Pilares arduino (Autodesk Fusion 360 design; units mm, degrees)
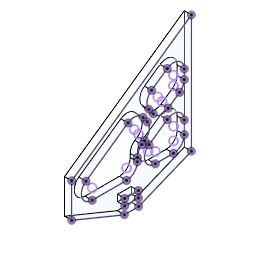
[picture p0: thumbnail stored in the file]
part number: 2026-07-18-00-36-09-592
sketch "Boceto1" plane through (0, 0, 0) normal (0, 0, 1) x axis (1, 0, 0)
  line L1 (3, 0) -> (0, 0)
  line L2 (3, 50) -> (3, 0)
  line L3 (0, 50) -> (3, 50)
  line L4 (0, 0) -> (0, 50)
  point P1 (0, 0)
  point P2 (0, 0)
  point P3 (3, 0)
  point P4 (3, 50)
  coincident P1 P2
  horizontal L1
  perpendicular L1 L2
  perpendicular L2 L3
  perpendicular L1 L4
  dimension "d1" distance P2 P3 = 3
  dimension "d2" distance P3 P4 = 50
extrude "Extruir1" new body sketch "Boceto1" along normal blind 62
sketch "Boceto2" plane through (3, 0, 0) normal (1, 0, 0) x axis (0, 1, 0)
  line L1 (50, 0) -> (0, 0)
  line L2 (50, 62) -> (50, 0)
  line L3 (0, 62) -> (50, 62)
  line L4 (0, 0) -> (0, 62)
  line L5 (50, 9) -> (50, 0)
  line L6 (25, 0) -> (50, 0)
  line L7 (28, 0) -> (25, 0)
  line L8 (50, 9) -> (28, 0)
  line L9 (22, 0) -> (25, 0)
  line L10 (0, 9) -> (0, 0)
  line L11 (22, 0) -> (0, 9)
  line L12 (0, 0) -> (22, 0)
  point P3 (50, 0)
  point P6 (50, 0)
  point P8 (25, 0)
  point P9 (28, 0)
  point P10 (22, 0)
  point P2 (0, 0)
  point P11 (0, 0)
  point P12 (0, 9)
  point P13 (0, 0)
  point P7 (50, 9)
  coincident P3 P6
  perpendicular L1 L5
  midpoint L1 P8
  coincident L1 P9
  coincident L1 P10
  coincident P2 P11
  coincident L4 P12
  coincident P2 P13
  dimension "d5" distance P6 P7 = 9
extrude "Extruir2" cut sketch "Boceto2" profile of L1 L2 L4 L5 L6 L8 L10 L11 L12 against normal blind 6
sketch "Boceto3" plane through (3, 0, 0) normal (1, 0, 0) x axis (0, 1, 0)
  line L1 (22, 0) -> (0, 9)
  line L2 (28, 0) -> (22, 0)
  line L3 (50, 9) -> (28, 0)
  line L4 (50, 62) -> (50, 9)
  line L5 (0, 62) -> (50, 62)
  line L6 (0, 9) -> (0, 62)
  line L7 (0, 24) -> (0, 9)
  line L8 (50, 62) -> (0, 24)
  line L9 (0, 62) -> (50, 62)
  line L10 (0, 24) -> (0, 62)
  point P2 (0, 9)
  point P8 (0, 9)
  point P6 (50, 62)
  point P10 (50, 62)
  point P11 (50, 62)
  point P7 (0, 62)
  point P12 (0, 62)
  point P13 (0, 62)
  point P9 (0, 24)
  coincident P2 P8
  parallel L6 L7
  coincident P6 P10
  coincident P6 P11
  coincident P7 P12
  coincident P7 P13
  dimension "d8" distance P8 P9 = 15
extrude "Extruir3" cut sketch "Boceto3" profile of L5 L6 L8 L9 L10 against normal blind 6
sketch "Boceto4" plane through (3, 0, 0) normal (1, 0, 0) x axis (0, 1, 0)
  line L1 (0, 24) -> (50, 62)
  line L2 (0, 9) -> (0, 24)
  line L3 (22, 0) -> (0, 9)
  line L4 (28, 0) -> (22, 0)
  line L5 (50, 9) -> (28, 0)
  line L6 (50, 62) -> (50, 9)
  line L7 (0, 27) -> (0, 9)
  line L8 (50, 65) -> (50, 9)
  line L9 (0, 27) -> (50, 65)
  point P4 (0, 9)
  point P8 (0, 9)
  point P7 (50, 9)
  point P10 (50, 9)
  point P9 (0, 27)
  point P11 (50, 65)
  coincident P4 P8
  parallel L2 L7
  coincident P7 P10
  parallel L6 L8
  dimension "d11" distance P8 P9 = 18
  dimension "d12" distance P10 P11 = 56
extrude "Extruir4" add sketch "Boceto4" profile of L1 L7 L8 L9 against normal blind 3
sketch "Boceto5" plane through (3, 0, 0) normal (1, 0, 0) x axis (0, 1, 0)
  line L1 (0, 9) -> (0, 27)
  line L2 (22, 0) -> (0, 9)
  line L3 (28, 0) -> (22, 0)
  line L4 (50, 9) -> (28, 0)
  line L5 (50, 65) -> (50, 9)
  line L6 (0, 27) -> (50, 65)
  line L7 (50, 62) -> (0, 27)
  line L8 (50, 62) -> (50, 65)
  line L9 (0, 27) -> (50, 65)
  point P2 (0, 27)
  point P8 (0, 27)
  point P9 (50, 62)
  point P7 (50, 65)
  point P10 (50, 65)
  point P11 (50, 65)
  point P12 (0, 27)
  coincident P2 P8
  coincident L5 P9
  coincident P7 P10
  coincident P7 P11
  coincident P2 P12
extrude "Extruir5" cut sketch "Boceto5" profile of L5 L6 L7 L8 L9 against normal blind 6
sketch "Boceto6" plane through (3, 0, 0) normal (1, 0, 0) x axis (0, 1, 0)
  line L1 (0, 27) -> (50, 62)
  line L2 (0, 9) -> (0, 27)
  line L3 (22, 0) -> (0, 9)
  line L4 (28, 0) -> (22, 0)
  line L5 (50, 9) -> (28, 0)
  line L6 (50, 62) -> (50, 9)
  line L7 (0, 12) -> (0, 9)
  line L8 (50, 12) -> (0, 12)
  line L9 (50, 12) -> (50, 9)
  line L10 (26.7204, 42.0423) -> (25, 44.5)
  line L11 (50, 58.338) -> (26.7204, 42.0423)
  line L12 (0, 23.338) -> (26.7204, 42.0423)
  line L13 (47, 12) -> (50, 12)
  line L14 (47, 56.238) -> (47, 12)
  line L15 (3, 12) -> (0, 12)
  line L16 (3, 25.438) -> (3, 12)
  line L17 (25, 12) -> (3, 12)
  line L18 (47, 34.119) -> (47, 56.238)
  line L19 (47, 34.119) -> (47, 56.238)
  line L20 (15.4, 12) -> (47, 34.119)
  line L21 (32.9203, 20.6018) -> (31.2, 23.0595)
  line L22 (47, 30.4571) -> (32.9203, 20.6018)
  line L23 (25.2826, 15.2556) -> (32.9203, 20.6018)
  line L24 (20.7418, 12.0772) -> (25.2826, 15.2556)
  line L25 (15.4, 12) -> (47, 34.119)
  line L26 (20.6315, 12) -> (15.4, 12)
  line L27 (47, 30.4571) -> (20.6315, 12)
  line L28 (39.9602, 25.5294) -> (32.9203, 20.6018)
  circle C1 centre (42.5, 21.8144) radius 4.5
  circle C2 centre (42.5, 16.5) radius 4.5
  circle C3 centre (34.9077, 16.5) radius 4.5
  circle C4 centre (42.5, 47.5951) radius 4.5
  circle C5 centre (42.5, 36.462) radius 4.5
  circle C6 centre (7.5, 16.5) radius 4.5
  circle C7 centre (7.5, 23.0951) radius 4.5
  circle C8 centre (13.9816, 16.5) radius 4.5
  point P4 (0, 9)
  point P8 (0, 9)
  point P9 (0, 12)
  point P10 (50, 12)
  point P7 (50, 9)
  point P11 (50, 9)
  point P12 (25, 44.5)
  point P14 (50, 58.338)
  point P15 (0, 23.338)
  point P16 (47, 12)
  point P17 (47, 56.238)
  point P18 (3, 12)
  point P19 (3, 25.438)
  point P20 (25, 12)
  point P21 (47, 34.119)
  point P22 (15.4, 12)
  point P23 (31.2, 23.0595)
  point P25 (47, 30.4571)
  point P28 (20.6315, 12)
  point P29 (39.9602, 25.5294)
  point P13 (26.7204, 42.0423)
  point P24 (32.9203, 20.6018)
  coincident P4 P8
  coincident L2 P9
  coincident L6 P10
  perpendicular L6 L8
  coincident P7 P11
  midpoint L1 P12
  perpendicular L1 L10
  coincident L6 P14
  perpendicular L10 L11
  coincident L2 P15
  perpendicular L10 L12
  coincident L8 P16
  coincident L11 P17
  perpendicular L13 L14
  coincident L8 P18
  coincident L12 P19
  perpendicular L15 L16
  midpoint L8 P20
  midpoint L14 P21
  coincident L8 P22
  midpoint L20 P23
  perpendicular L20 L21
  coincident L14 P25
  perpendicular L21 L22
  perpendicular L21 L23
  parallel L23 L24
  coincident L17 P28
  midpoint L22 P29
  tangent L28 C1
  tangent L14 C1
  tangent L14 C2
  tangent L8 C2
  tangent L8 C3
  tangent L23 C3
  tangent L14 C4
  tangent L11 C4
  tangent L25 C5
  tangent L18 C5
  tangent L12 C7
  tangent L16 C7
  tangent L16 C6
  tangent L17 C6
  tangent L8 C8
  tangent L20 C8
  dimension "d17" distance P12 P13 = 3
  dimension "d18" distance P23 P24 = 3
  dimension "d19" diameter C1 = 9
  dimension "d20" diameter C2 = 9
  dimension "d21" diameter C3 = 9
  dimension "d22" diameter C4 = 9
  dimension "d23" diameter C5 = 9
  dimension "d24" diameter C6 = 9
  dimension "d25" diameter C7 = 9
  dimension "d26" diameter C8 = 9
extrude "Extruir6" cut sketch "Boceto6" profile of L8 L11 L12 L14 L16 L17 L18 L19 L20 L22 L23 L25 L27 L28 C1 C2 C3 C4 C5 C6 C7 C8 against normal blind 6
sketch "Boceto7" plane through (3, 0, 0) normal (1, 0, 0) x axis (0, 1, 0)
  line L1 (7.5014, 12) -> (13.9822, 12)
  line L2 (3, 23.0951) -> (3, 16.5)
  line L3 (39.9194, 51.2816) -> (4.9194, 26.7816)
  line L4 (47, 36.462) -> (47, 47.5951)
  line L5 (16.5621, 12.8134) -> (45.0805, 32.7754)
  line L6 (34.9081, 12) -> (42.5006, 12)
  line L7 (39.9195, 25.501) -> (32.3272, 20.1866)
  line L8 (47, 16.5) -> (47, 21.8144)
  line L9 (0, 27) -> (50, 62)
  line L10 (0, 9) -> (0, 27)
  line L11 (22, 0) -> (0, 9)
  line L12 (28, 0) -> (22, 0)
  line L13 (50, 9) -> (28, 0)
  line L14 (50, 62) -> (50, 9)
  line L15 (22, 3) -> (22, 0)
  line L16 (28, 3) -> (22, 3)
  line L17 (28, 6) -> (28, 3)
  line L18 (22, 6) -> (28, 6)
  line L19 (22, 3) -> (22, 6)
  line L20 (22.1552, 5.8667) -> (22.1552, 3.1667)
  line L21 (27.8552, 3.1667) -> (27.8552, 5.8667)
  line L22 (22.1552, 3.1667) -> (27.8552, 3.1667)
  line L23 (27.8552, 5.8667) -> (22.1552, 5.8667)
  arc A1 centre (7.5, 16.5) radius 4.5 clockwise from (7.5014, 12) to (3, 16.5)
  arc A2 centre (7.5, 23.0951) radius 4.5 clockwise from (3, 23.0951) to (4.9194, 26.7816)
  arc A3 centre (42.5, 47.5951) radius 4.5 clockwise from (39.9194, 51.2816) to (47, 47.5951)
  arc A4 centre (42.5, 36.462) radius 4.5 clockwise from (47, 36.462) to (45.0805, 32.7754)
  arc A5 centre (13.9816, 16.5) radius 4.5 clockwise from (16.5621, 12.8134) to (13.9822, 12)
  arc A6 centre (34.9077, 16.5) radius 4.5 clockwise from (34.9081, 12) to (32.3272, 20.1866)
  arc A7 centre (42.5, 21.8144) radius 4.5 clockwise from (39.9195, 25.501) to (47, 21.8144)
  arc A8 centre (42.5, 16.5) radius 4.5 clockwise from (47, 16.5) to (42.5006, 12)
  point P29 (22, 0)
  point P32 (22, 0)
  coincident P29 P32
  perpendicular L12 L15
  perpendicular L15 L16
  perpendicular L16 L17
  perpendicular L17 L18
  perpendicular L16 L19
extrude "Extruir7" cut sketch "Boceto7" profile of L16 L17 L18 L19 against normal blind 6
sketch "Boceto8" plane through (3, 0, 0) normal (1, 0, 0) x axis (0, 1, 0)
  line L1 (22, 3) -> (28, 3)
  line L2 (22, 6) -> (22, 3)
  line L3 (28, 6) -> (22, 6)
  line L4 (28, 3) -> (28, 6)
  line L5 (7.5014, 12) -> (13.9822, 12)
  line L6 (3, 23.0951) -> (3, 16.5)
  line L7 (39.9194, 51.2816) -> (4.9194, 26.7816)
  line L8 (47, 36.462) -> (47, 47.5951)
  line L9 (16.5621, 12.8134) -> (45.0805, 32.7754)
  line L10 (34.9081, 12) -> (42.5006, 12)
  line L11 (39.9195, 25.501) -> (32.3272, 20.1866)
  line L12 (47, 16.5) -> (47, 21.8144)
  line L13 (0, 27) -> (50, 62)
  line L14 (0, 9) -> (0, 27)
  line L15 (22, 0) -> (0, 9)
  line L16 (28, 0) -> (22, 0)
  line L17 (50, 9) -> (28, 0)
  line L18 (50, 62) -> (50, 9)
  line L19 (39.9194, 51.2816) -> (4.9194, 26.7816)
  line L20 (57.0546, 63.2763) -> (39.9194, 51.2816)
  line L21 (-4.5642, 20.1431) -> (57.0546, 63.2763)
  line L22 (50, 35.5) -> (50, 58.338)
  line L23 (0, 13) -> (0, 23.338)
  line L24 (29.686, 36.7943) -> (26.2452, 41.7097)
  line L25 (41.9336, 45.3676) -> (29.686, 36.7943)
  line L26 (-9.9761, 9.0308) -> (41.9336, 45.3676)
  line L27 (67.0038, 62.9168) -> (-9.9761, 9.0308)
  line L28 (50, 62) -> (50, 58.338)
  line L29 (0, 27) -> (50, 62)
  line L30 (0, 23.338) -> (0, 27)
  line L31 (47, 57.2789) -> (47, 43)
  line L32 (3, 26.5) -> (3, 19.7975)
  line L33 (47, 39.5) -> (47, 48.9141)
  line L34 (3, 13.3175) -> (3, 26.5)
  line L35 (3, 12) -> (8.5412, 12)
  line L36 (3, 12) -> (3, 13.3175)
  arc A1 centre (7.5, 16.5) radius 4.5 clockwise from (7.5014, 12) to (3, 16.5)
  arc A2 centre (7.5, 23.0951) radius 4.5 clockwise from (3, 23.0951) to (4.9194, 26.7816)
  arc A3 centre (42.5, 47.5951) radius 4.5 clockwise from (39.9194, 51.2816) to (47, 47.5951)
  arc A4 centre (42.5, 36.462) radius 4.5 clockwise from (47, 36.462) to (45.0805, 32.7754)
  arc A5 centre (13.9816, 16.5) radius 4.5 clockwise from (16.5621, 12.8134) to (13.9822, 12)
  arc A6 centre (34.9077, 16.5) radius 4.5 clockwise from (34.9081, 12) to (32.3272, 20.1866)
  arc A7 centre (42.5, 21.8144) radius 4.5 clockwise from (39.9195, 25.501) to (47, 21.8144)
  arc A8 centre (42.5, 16.5) radius 4.5 clockwise from (47, 16.5) to (42.5006, 12)
  circle C1 centre (42.5, 40.2712) radius 4.5
  circle C2 centre (8.5412, 16.5) radius 4.5
  point P11 (4.9194, 26.7816)
  point P36 (4.9194, 26.7816)
  point P13 (39.9194, 51.2816)
  point P37 (39.9194, 51.2816)
  point P38 (39.9194, 51.2816)
  point P41 (50, 58.338)
  point P42 (50, 35.5)
  point P43 (0, 23.338)
  point P44 (0, 13)
  point P45 (26.2452, 41.7097)
  point P30 (50, 62)
  point P50 (50, 62)
  point P51 (50, 62)
  point P31 (0, 27)
  point P52 (0, 27)
  point P53 (0, 27)
  point P54 (47, 43)
  point P56 (3, 19.7975)
  point P58 (47, 48.9141)
  point P59 (47, 39.5)
  point P63 (8.5412, 12)
  point P46 (29.686, 36.7943)
  coincident P11 P36
  coincident P13 P37
  coincident P13 P38
  tangent A3 L20
  parallel L7 L21
  coincident L21 P41
  coincident L18 P41
  midpoint L18 P42
  coincident L14 P43
  coincident L21 P43
  coincident L14 P44
  midpoint L21 P45
  perpendicular L7 L24
  perpendicular L24 L25
  parallel L25 L26
  parallel L26 L27
  coincident P30 P50
  coincident P30 P51
  coincident P31 P52
  coincident P31 P53
  coincident L8 P54
  parallel L30 L31
  midpoint L6 P56
  parallel L6 L32
  coincident L27 P58
  coincident L31 P58
  coincident L8 P59
  parallel L33 L34
  tangent L33 C1
  tangent L27 C1
  tangent L26 C2
  tangent L5 C2
  coincident L5 P63
  coincident C2 P63
  tangent C2 L35
  parallel L5 L35
  parallel L34 L36
  dimension "d31" distance P45 P46 = 6
  dimension "d32" diameter C1 = 9
  dimension "d33" diameter C2 = 9
extrude "Extruir8" cut sketch "Boceto8" profile of L7 L13 L14 L18 L19 L20 L21 L28 L29 L30 against normal blind 6
extrude "Extruir9" add sketch "Boceto8" profile of L5 A1 L6 A2 L7 A3 L8 L19 L21 L24 L25 L26 L27 L31 L32 L33 L34 C1 C2 L35 against normal blind 3
sketch "Boceto9" plane through (3, 0, 0) normal (1, 0, 0) x axis (0, 1, 0)
  line L1 (47, 36.462) -> (47, 40.2712)
  line L2 (16.5621, 12.8134) -> (45.0805, 32.7754)
  line L3 (8.5412, 12) -> (13.9822, 12)
  line L4 (39.9194, 43.9577) -> (5.9606, 20.1865)
  line L5 (34.9081, 12) -> (42.5006, 12)
  line L6 (39.9195, 25.501) -> (32.3272, 20.1866)
  line L7 (47, 16.5) -> (47, 21.8144)
  line L8 (0, 23.338) -> (50, 58.338)
  line L9 (0, 9) -> (0, 23.338)
  line L10 (22, 0) -> (0, 9)
  line L11 (28, 0) -> (22, 0)
  line L12 (50, 9) -> (28, 0)
  line L13 (50, 58.338) -> (50, 9)
  line L14 (22, 3) -> (28, 3)
  line L15 (22, 6) -> (22, 3)
  line L16 (28, 6) -> (22, 6)
  line L17 (28, 3) -> (28, 6)
  line L18 (30.4077, 16.5) -> (47, 16.5)
  line L19 (27.4077, 16.5) -> (30.4077, 16.5)
  line L20 (27.4077, 20.405) -> (27.4077, 16.5)
  line L21 (27.4077, 12) -> (13.9822, 12)
  line L22 (27.4077, 16.5) -> (27.4077, 12)
  line L23 (13.9822, 12) -> (27.4077, 20.405)
  line L24 (22.9077, 16.5) -> (22.9077, 12)
  line L25 (16.5621, 12.8134) -> (45.0805, 32.7754)
  arc A1 centre (42.5, 36.462) radius 4.5 clockwise from (47, 36.462) to (45.0805, 32.7754)
  arc A2 centre (13.9816, 16.5) radius 4.5 clockwise from (16.5621, 12.8134) to (13.9822, 12)
  arc A3 centre (8.5412, 16.5) radius 4.5 clockwise from (8.5412, 12) to (5.9606, 20.1865)
  arc A4 centre (42.5, 40.2712) radius 4.5 clockwise from (39.9194, 43.9577) to (47, 40.2712)
  arc A5 centre (34.9077, 16.5) radius 4.5 clockwise from (34.9081, 12) to (32.3272, 20.1866)
  arc A6 centre (42.5, 21.8144) radius 4.5 clockwise from (39.9195, 25.501) to (47, 21.8144)
  arc A7 centre (42.5, 16.5) radius 4.5 clockwise from (47, 16.5) to (42.5006, 12)
  circle C1 centre (22.9077, 16.5) radius 4.5
  circle C2 centre (31.9077, 18.062) radius 4.5
  point P21 (47, 16.5)
  point P33 (47, 16.5)
  point P34 (30.4077, 16.5)
  point P36 (27.4077, 20.405)
  point P7 (13.9822, 12)
  point P37 (13.9822, 12)
  point P39 (13.9822, 12)
  point P40 (22.9077, 12)
  point P41 (22.9077, 16.5)
  point P42 (22.9077, 16.5)
  point P35 (27.4077, 16.5)
  coincident P21 P33
  coincident A5 P34
  perpendicular L7 L18
  parallel L18 L19
  coincident L2 P36
  perpendicular L19 L20
  coincident P7 P37
  perpendicular L20 L21
  perpendicular L19 L22
  coincident P7 P39
  coincident L21 P40
  perpendicular L21 L24
  coincident P41 P42
  tangent L22 C1
  tangent C2 L25
  tangent L20 C2
  dimension "d38" distance P34 P35 = 3
  dimension "d41" distance P40 P41 = 4.5
  dimension "d42" diameter C1 = 9
  dimension "d45" diameter C2 = 9
extrude "Extruir10" cut sketch "Boceto9" profile of L2 A2 L20 L21 L22 against normal blind 4
extrude "Extruir11" add sketch "Boceto9" profile of L21 L22 C1 against normal blind 3
extrude "Extruir12" cut sketch "Boceto9" profile of L2 L20 C2 L25 against normal blind 3
sketch "Boceto10" plane through (3, 0, 0) normal (1, 0, 0) x axis (0, 1, 0)
  line L1 (22, 3) -> (28, 3)
  line L2 (22, 6) -> (22, 3)
  line L3 (28, 6) -> (22, 6)
  line L4 (28, 3) -> (28, 6)
  line L5 (0, 23.338) -> (50, 58.338)
  line L6 (0, 9) -> (0, 23.338)
  line L7 (22, 0) -> (0, 9)
  line L8 (28, 0) -> (22, 0)
  line L9 (50, 9) -> (28, 0)
  line L10 (50, 58.338) -> (50, 9)
  line L11 (34.9081, 12) -> (42.5006, 12)
  line L12 (39.9195, 25.501) -> (32.3272, 20.1866)
  line L13 (47, 16.5) -> (47, 21.8144)
  line L14 (27.4077, 16.5) -> (27.4077, 18.062)
  line L15 (8.5412, 12) -> (22.9077, 12)
  line L16 (39.9194, 43.9577) -> (5.9606, 20.1865)
  line L17 (47, 36.462) -> (47, 40.2712)
  line L18 (29.3272, 21.7486) -> (45.0805, 32.7754)
  line L19 (39.9194, 43.9577) -> (5.9606, 20.1865)
  line L20 (28.4408, 35.9226) -> (25, 40.838)
  line L21 (29.6694, 36.7827) -> (36.62, 26.8533)
  line L22 (34.1622, 25.133) -> (30.6871, 30.0977)
  line L23 (27.2117, 35.0623) -> (34.1622, 25.133)
  line L24 (41.9336, 45.3676) -> (29.686, 36.7943)
  line L25 (16.5621, 12.8134) -> (45.0805, 32.7754)
  line L26 (67.0038, 62.9168) -> (-9.9761, 9.0308)
  arc A1 centre (34.9077, 16.5) radius 4.5 clockwise from (34.9081, 12) to (32.3272, 20.1866)
  arc A2 centre (42.5, 21.8144) radius 4.5 clockwise from (39.9195, 25.501) to (47, 21.8144)
  arc A3 centre (42.5, 16.5) radius 4.5 clockwise from (47, 16.5) to (42.5006, 12)
  arc A4 centre (31.9077, 18.062) radius 4.5 clockwise from (27.4077, 18.062) to (29.3272, 21.7486)
  arc A5 centre (22.9077, 16.5) radius 4.5 clockwise from (27.4077, 16.5) to (22.9077, 12)
  arc A6 centre (8.5412, 16.5) radius 4.5 clockwise from (8.5412, 12) to (5.9606, 20.1865)
  arc A7 centre (42.5, 40.2712) radius 4.5 clockwise from (39.9194, 43.9577) to (47, 40.2712)
  arc A8 centre (42.5, 36.462) radius 4.5 clockwise from (47, 36.462) to (45.0805, 32.7754)
  circle C1 centre (35.9365, 35.6767) radius 4.5
  circle C2 centre (37.726, 33.1204) radius 4.5
  circle C3 centre (26.1058, 28.7952) radius 4.5
  point P28 (5.9606, 20.1865)
  point P36 (5.9606, 20.1865)
  point P30 (39.9194, 43.9577)
  point P37 (39.9194, 43.9577)
  point P38 (25, 40.838)
  point P39 (28.4408, 35.9226)
  point P41 (36.62, 26.8533)
  point P42 (29.6694, 36.7827)
  point P43 (34.1622, 25.133)
  point P44 (27.2117, 35.0623)
  coincident P28 P36
  coincident P30 P37
  midpoint L5 P38
  coincident L19 P39
  perpendicular L19 L20
  coincident L18 P41
  coincident L19 P42
  perpendicular L19 L21
  coincident L18 P43
  perpendicular L18 L22
  coincident L19 P44
  perpendicular L19 L23
  tangent C1 L24
  tangent L21 C1
  tangent C2 L25
  tangent C3 L26
  tangent L23 C3
  tangent L21 C2
  dimension "d50" diameter C1 = 9
  dimension "d51" diameter C2 = 9
  dimension "d52" diameter C3 = 9
extrude "Extruir13" add sketch "Boceto10" profile of L16 L18 L19 L21 L23 C1 L24 C2 L25 C3 L26 against normal blind 3
sketch "Boceto11" plane through (3, 0, 0) normal (1, 0, 0) x axis (0, 1, 0)
  line L1 (29.7923, 31.3758) -> (34.1622, 25.133)
  line L2 (16.5621, 12.8134) -> (45.0805, 32.7754)
  circle C1 centre (27.8951, 26.239) radius 4.5
  tangent C1 L2
  tangent L1 C1
  dimension "d57" diameter C1 = 9
extrude "Extruir14" add sketch "Boceto11" against normal blind 3
sketch "Boceto12" plane through (3, 0, 0) normal (1, 0, 0) x axis (0, 1, 0)
  line L1 (39.9194, 43.9577) -> (33.3559, 39.3632)
  line L2 (47, 36.462) -> (47, 40.2712)
  line L3 (40.3066, 29.4338) -> (45.0805, 32.7754)
  line L4 (32.25, 33.0961) -> (34.0395, 30.5398)
  line L5 (22, 3) -> (28, 3)
  line L6 (22, 6) -> (22, 3)
  line L7 (28, 6) -> (22, 6)
  line L8 (28, 3) -> (28, 6)
  line L9 (0, 23.338) -> (50, 58.338)
  line L10 (0, 9) -> (0, 23.338)
  line L11 (22, 0) -> (0, 9)
  line L12 (28, 0) -> (22, 0)
  line L13 (50, 9) -> (28, 0)
  line L14 (50, 58.338) -> (50, 9)
  line L15 (34.9081, 12) -> (42.5006, 12)
  line L16 (39.9195, 25.501) -> (32.3272, 20.1866)
  line L17 (47, 16.5) -> (47, 21.8144)
  line L18 (31.5816, 28.8196) -> (29.7923, 31.3758)
  line L19 (29.3272, 21.7486) -> (30.4756, 22.5525)
  line L20 (27.4077, 16.5) -> (27.4077, 18.062)
  line L21 (8.5412, 12) -> (22.9077, 12)
  line L22 (23.5252, 32.4817) -> (5.9606, 20.1865)
  line L23 (13.9822, 12) -> (27.4077, 20.405)
  line L24 (8.5412, 12) -> (13.9822, 12)
  line L25 (13.0412, 16.5) -> (8.5412, 16.5)
  line L26 (13.0412, 25.143) -> (13.0412, 16.5)
  line L27 (13.0412, 12) -> (13.0412, 16.5)
  line L28 (16.0412, 16.5) -> (13.0412, 16.5)
  line L29 (16.0412, 27.243) -> (16.0412, 16.5)
  line L30 (16.0412, 12) -> (16.0412, 16.5)
  line L31 (-9.9761, 9.0308) -> (41.9336, 45.3676)
  line L32 (27.4077, 12) -> (13.9822, 12)
  arc A1 centre (42.5, 40.2712) radius 4.5 clockwise from (39.9194, 43.9577) to (47, 40.2712)
  arc A2 centre (42.5, 36.462) radius 4.5 clockwise from (47, 36.462) to (45.0805, 32.7754)
  arc A3 centre (37.726, 33.1204) radius 4.5 clockwise from (40.3066, 29.4338) to (34.0395, 30.5398)
  arc A4 centre (35.9365, 35.6767) radius 4.5 clockwise from (32.25, 33.0961) to (33.3559, 39.3632)
  arc A5 centre (34.9077, 16.5) radius 4.5 clockwise from (34.9081, 12) to (32.3272, 20.1866)
  arc A6 centre (42.5, 21.8144) radius 4.5 clockwise from (39.9195, 25.501) to (47, 21.8144)
  arc A7 centre (42.5, 16.5) radius 4.5 clockwise from (47, 16.5) to (42.5006, 12)
  arc A8 centre (26.1058, 28.7952) radius 4.5 clockwise from (23.5252, 32.4817) to (29.7923, 31.3758)
  arc A9 centre (27.8951, 26.239) radius 4.5 clockwise from (31.5816, 28.8196) to (30.4756, 22.5525)
  arc A10 centre (31.9077, 18.062) radius 4.5 clockwise from (27.4077, 18.062) to (29.3272, 21.7486)
  arc A11 centre (22.9077, 16.5) radius 4.5 clockwise from (27.4077, 16.5) to (22.9077, 12)
  arc A12 centre (8.5412, 16.5) radius 4.5 clockwise from (8.5412, 12) to (5.9606, 20.1865)
  circle C1 centre (8.5412, 16.5) radius 4.5
  circle C2 centre (20.5412, 24.9) radius 4.5
  circle C3 centre (20.5412, 16.5) radius 4.5
  point P49 (13.9822, 12)
  point P50 (13.9822, 12)
  point P45 (8.5412, 12)
  point P51 (8.5412, 12)
  point P47 (8.5412, 16.5)
  point P53 (8.5412, 16.5)
  point P54 (13.0412, 16.5)
  point P55 (13.0412, 25.143)
  point P56 (13.0412, 12)
  point P58 (16.0412, 27.243)
  point P59 (16.0412, 12)
  point P57 (16.0412, 16.5)
  coincident P49 P50
  coincident P45 P51
  coincident P47 P53
  coincident C1 P54
  horizontal L25
  coincident L22 P55
  tangent C1 L26
  coincident L24 P56
  tangent C1 L27
  perpendicular L26 L28
  coincident L22 P58
  perpendicular L28 L29
  coincident L21 P59
  perpendicular L21 L30
  tangent C2 L31
  tangent L29 C2
  tangent C3 L32
  tangent L30 C3
  dimension "d60" distance P54 P57 = 3
  dimension "d61" diameter C2 = 9
  dimension "d62" diameter C3 = 9
extrude "Extruir15" add of existing geometry blind 0.15
extrude "Extruir16" add of existing geometry blind 0.15
extrude "Extruir17" add of existing geometry blind 0.15
extrude "Extruir19" add of existing geometry blind 0.15
sketch "Boceto13" plane through (0, 0, 0) normal (-1, 0, 0) x axis (0, -1, 0)
  line L1 (-5.9606, 20.1865) -> (-23.5252, 32.4817)
  line L2 (-22.9077, 12) -> (-8.5412, 12)
  line L3 (-27.4077, 18.062) -> (-27.4077, 16.5)
  line L4 (-30.4756, 22.5525) -> (-29.3272, 21.7486)
  line L5 (-29.7923, 31.3758) -> (-31.5816, 28.8196)
  line L6 (-34.0395, 30.5398) -> (-32.25, 33.0961)
  line L7 (-45.0805, 32.7754) -> (-40.3066, 29.4338)
  line L8 (-47, 40.2712) -> (-47, 36.462)
  line L9 (-33.3559, 39.3632) -> (-39.9194, 43.9577)
  line L10 (-42.5006, 12) -> (-34.9081, 12)
  line L11 (-47, 21.8144) -> (-47, 16.5)
  line L12 (-32.3272, 20.1866) -> (-39.9195, 25.501)
  line L13 (-27.85, 3.15) -> (-22.15, 3.15)
  line L14 (-27.85, 5.85) -> (-27.85, 3.15)
  line L15 (-22.15, 5.85) -> (-27.85, 5.85)
  line L16 (-22.15, 3.15) -> (-22.15, 5.85)
  line L17 (-50, 58.338) -> (0, 23.338)
  line L18 (-50, 9) -> (-50, 58.338)
  line L19 (-28, 0) -> (-50, 9)
  line L20 (-22, 0) -> (-28, 0)
  line L21 (0, 9) -> (-22, 0)
  line L22 (0, 23.338) -> (0, 9)
  arc A1 centre (-8.5412, 16.5) radius 4.5 clockwise from (-5.9606, 20.1865) to (-8.5412, 12)
  arc A2 centre (-22.9077, 16.5) radius 4.5 clockwise from (-22.9077, 12) to (-27.4077, 16.5)
  arc A3 centre (-31.9077, 18.062) radius 4.5 clockwise from (-29.3272, 21.7486) to (-27.4077, 18.062)
  arc A4 centre (-27.8951, 26.239) radius 4.5 clockwise from (-30.4756, 22.5525) to (-31.5816, 28.8196)
  arc A5 centre (-26.1058, 28.7952) radius 4.5 clockwise from (-29.7923, 31.3758) to (-23.5252, 32.4817)
  arc A6 centre (-35.9365, 35.6767) radius 4.5 clockwise from (-33.3559, 39.3632) to (-32.25, 33.0961)
  arc A7 centre (-37.726, 33.1204) radius 4.5 clockwise from (-34.0395, 30.5398) to (-40.3066, 29.4338)
  arc A8 centre (-42.5, 36.462) radius 4.5 clockwise from (-45.0805, 32.7754) to (-47, 36.462)
  arc A9 centre (-42.5, 40.2712) radius 4.5 clockwise from (-47, 40.2712) to (-39.9194, 43.9577)
  arc A10 centre (-42.5, 16.5) radius 4.5 clockwise from (-42.5006, 12) to (-47, 16.5)
  arc A11 centre (-42.5, 21.8144) radius 4.5 clockwise from (-47, 21.8144) to (-39.9195, 25.501)
  arc A12 centre (-34.9077, 16.5) radius 4.5 clockwise from (-32.3272, 20.1866) to (-34.9081, 12)
sketch "Boceto14" plane through (3, 0, 0) normal (1, 0, 0) x axis (0, 1, 0)
  line L1 (39.9194, 43.9577) -> (33.3559, 39.3632)
  line L2 (47, 36.462) -> (47, 40.2712)
  line L3 (40.3066, 29.4338) -> (45.0805, 32.7754)
  line L4 (32.25, 33.0961) -> (34.0395, 30.5398)
  line L5 (22.15, 5.85) -> (22.15, 3.15)
  line L6 (27.85, 5.85) -> (22.15, 5.85)
  line L7 (27.85, 3.15) -> (27.85, 5.85)
  line L8 (22.15, 3.15) -> (27.85, 3.15)
  line L9 (0, 23.338) -> (50, 58.338)
  line L10 (0, 9) -> (0, 23.338)
  line L11 (22, 0) -> (0, 9)
  line L12 (28, 0) -> (22, 0)
  line L13 (50, 9) -> (28, 0)
  line L14 (50, 58.338) -> (50, 9)
  line L15 (34.9081, 12) -> (42.5006, 12)
  line L16 (39.9195, 25.501) -> (32.3272, 20.1866)
  line L17 (47, 16.5) -> (47, 21.8144)
  line L18 (31.5816, 28.8196) -> (29.7923, 31.3758)
  line L19 (29.3272, 21.7486) -> (30.4756, 22.5525)
  line L20 (27.4077, 16.5) -> (27.4077, 18.062)
  line L21 (8.5412, 12) -> (22.9077, 12)
  line L22 (23.5252, 32.4817) -> (5.9606, 20.1865)
  arc A1 centre (42.5, 40.2712) radius 4.5 clockwise from (39.9194, 43.9577) to (47, 40.2712)
  arc A2 centre (42.5, 36.462) radius 4.5 clockwise from (47, 36.462) to (45.0805, 32.7754)
  arc A3 centre (37.726, 33.1204) radius 4.5 clockwise from (40.3066, 29.4338) to (34.0395, 30.5398)
  arc A4 centre (35.9365, 35.6767) radius 4.5 clockwise from (32.25, 33.0961) to (33.3559, 39.3632)
  arc A5 centre (34.9077, 16.5) radius 4.5 clockwise from (34.9081, 12) to (32.3272, 20.1866)
  arc A6 centre (42.5, 21.8144) radius 4.5 clockwise from (39.9195, 25.501) to (47, 21.8144)
  arc A7 centre (42.5, 16.5) radius 4.5 clockwise from (47, 16.5) to (42.5006, 12)
  arc A8 centre (26.1058, 28.7952) radius 4.5 clockwise from (23.5252, 32.4817) to (29.7923, 31.3758)
  arc A9 centre (27.8951, 26.239) radius 4.5 clockwise from (31.5816, 28.8196) to (30.4756, 22.5525)
  arc A10 centre (31.9077, 18.062) radius 4.5 clockwise from (27.4077, 18.062) to (29.3272, 21.7486)
  arc A11 centre (22.9077, 16.5) radius 4.5 clockwise from (27.4077, 16.5) to (22.9077, 12)
  arc A12 centre (8.5412, 16.5) radius 4.5 clockwise from (8.5412, 12) to (5.9606, 20.1865)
